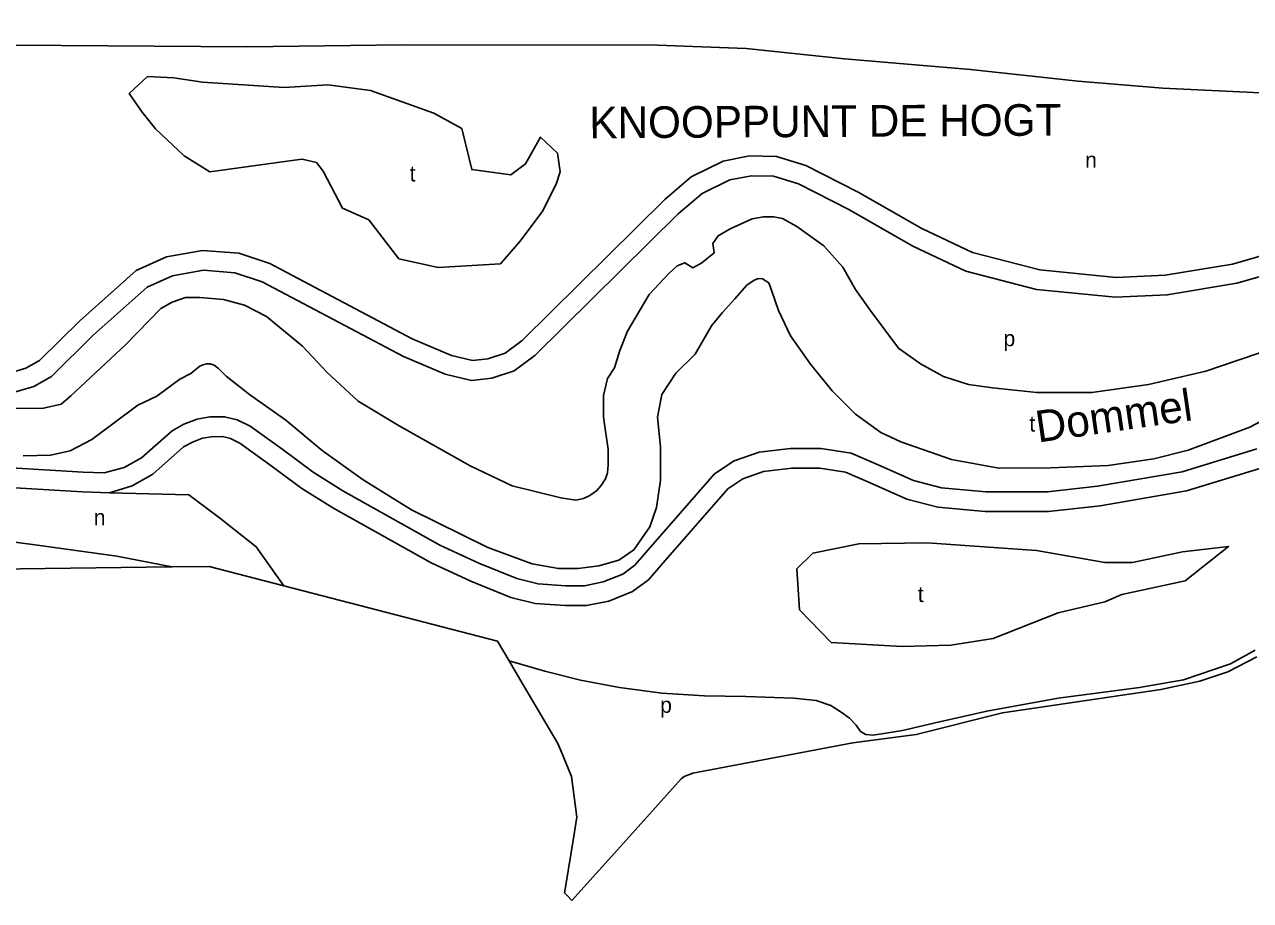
# Model space of a CAD drawing. Extents: x 157646 to 159241, y 379213 to 381217.
# Drawn here: x 157924.6 to 158234.9, y 379212.5 to 379434.4 of the extents above; entities that cross this region are included whole.
import ezdxf

# ---------------------------------------------------------------- set-up
doc = ezdxf.new("R2010")
doc.units = 0
for name, color, linetype in [('BLT_Basislijn', 7, 'Continuous'), ('BLT_Centroide', 7, 'Continuous'), ('BLT_Gemeentegrens', 7, 'Continuous'), ('BLT_Straatnaam_hoofdweg', 7, 'Continuous'), ('BLT_Vlakafsluiter', 7, 'Continuous'), ('BLT_Waternaam_spoorwegen', 7, 'Continuous')]:
    doc.layers.add(name, color=color, linetype=linetype)

msp = doc.modelspace()

# ---------------------------------------------------------------- linework, layer by layer
at = {"layer": 'BLT_Basislijn'}
for points in [[(158308.08, 379434.36), (158304.89, 379420.42), (158304.51, 379418.26), (158303.7, 379416.73), (158301.68, 379415.14), (158298.37, 379414.29), (158293.42, 379414.16), (158286.33, 379415.05), (158269.88, 379415.95), (158256.93, 379416.11), (158212.73, 379418.23), (158191.26, 379420.04), (158164.06, 379422.99), (158132.14, 379425.65), (158107.23, 379428.27), (158084.78, 379429.09), (158020.06, 379429.21), (157981.06, 379428.72), (157922.04, 379429.13), (157868.95, 379431.58), (157838.47, 379433.55)], [(158327.61, 379415.93), (158321.88, 379409.59), (158317.43, 379405.76), (158308.19, 379397.05), (158298.53, 379387.87), (158285.32, 379377.1), (158270.25, 379367.26), (158255.08, 379358.93), (158240.75, 379352.37), (158223.61, 379346.56), (158209.1, 379343.19), (158194.77, 379341.2)], [(158146.42, 379328.7), (158159.26, 379324.21), (158171.21, 379321.96), (158184.25, 379322.05), (158198.87, 379322.69), (158210.48, 379324.39), (158219.12, 379326.55), (158234.71, 379332.37), (158245.04, 379337.84), (158250.49, 379341.13), (158261.45, 379345.82), (158270.62, 379350.97), (158279.05, 379356.03), (158293.9, 379365.97), (158305.21, 379374.66), (158315.7, 379383.84), (158326.35, 379393.02), (158334.71, 379401.71), (158339.91, 379408.18)], [(158247.02, 379378.45), (158230.37, 379373.7), (158213.33, 379370.84), (158200.9, 379370.28), (158181.63, 379372.19), (158164.55, 379376.61), (158151.73, 379382.69), (158135.6, 379391.87), (158122.39, 379398.68), (158114.93, 379400.97), (158108.12, 379401.06), (158101.47, 379399.75), (158093.37, 379395.75), (158086.64, 379390.07), (158050.52, 379354.31), (158046.22, 379351.13), (158041.84, 379349.72), (158037.99, 379349.25), (158032.66, 379350.54), (158022.68, 379354.79), (157986.71, 379373.84), (157978.81, 379376.41), (157969.64, 379377.14), (157960.56, 379375.52), (157952.88, 379372.04), (157938.58, 379359.29), (157928.37, 379349.26), (157924.96, 379347.3), (157920.44, 379346)], [(158248.63, 379373.71), (158231.48, 379368.82), (158213.86, 379365.86), (158200.76, 379365.27), (158180.75, 379367.25), (158162.84, 379371.88), (158149.42, 379378.26), (158133.22, 379387.47), (158120.49, 379394.03), (158114.14, 379395.98), (158108.58, 379396.05), (158103.09, 379394.98), (158096.13, 379391.53), (158090.02, 379386.38), (158053.78, 379350.5), (158048.53, 379346.62), (158042.91, 379344.81), (158037.7, 379344.18), (158031.08, 379345.78), (158020.53, 379350.27), (157984.75, 379369.22), (157977.82, 379371.48), (157969.88, 379372.11), (157962.06, 379370.71), (157955.63, 379367.8), (157942, 379355.64), (157931.42, 379345.25), (157926.93, 379342.66), (157921.48, 379341.1)], [(158194.77, 379341.2), (158180.83, 379341.2), (158169.64, 379342.37), (158163.5, 379343.17), (158157.23, 379345.17), (158151.38, 379348.39), (158145.79, 379352.37), (158138.68, 379362), (158134.91, 379367.21), (158131.73, 379372.89), (158126.94, 379378.27), (158120.09, 379383.24), (158116.43, 379385.23), (158114.23, 379385.69), (158111.61, 379385.69), (158108.81, 379385.13), (158103.18, 379382.65), (158100.17, 379380.81), (158098.85, 379378.9), (158099.18, 379376.53), (158096.01, 379374.03), (158093.75, 379372.75), (158091.72, 379374.03), (158089.76, 379373.21), (158087.65, 379371.33), (158082.73, 379365.95), (158077.23, 379356.68), (158075.27, 379351.76), (158073.94, 379347.38), (158072.15, 379344.69), (158071.17, 379340.41), (158071.17, 379334.95), (158072.35, 379326.7), (158072.35, 379322.81), (158072.15, 379320.8), (158071.66, 379319.29), (158070.58, 379317.62), (158069.36, 379316.22), (158067.72, 379315.04), (158066.06, 379314.32), (158064.15, 379313.93), (158060.34, 379314.44), (158048.01, 379317.56), (158037.42, 379322.56), (158019.46, 379332.71), (158009.01, 379338.98), (158001.17, 379346.26), (157994.94, 379352.87), (157985.81, 379360.44), (157980.27, 379363.27), (157974.97, 379364.7), (157968.96, 379365.24), (157965.31, 379365.24), (157961.94, 379364.07), (157959.11, 379362.4), (157950.13, 379353.2), (157936.34, 379340.33), (157933.85, 379338.23), (157929.42, 379337.15), (157912.66, 379337.04)], [(157924.23, 379325.09), (157931.14, 379325.29), (157936.16, 379326.4), (157941.62, 379329.24), (157953.27, 379337.93), (157958.09, 379340.19), (157963.93, 379344.56), (157966.68, 379345.96), (157968.15, 379347.19), (157968.96, 379347.86), (157969.69, 379348.17), (157970.72, 379348.46), (157971.58, 379348.46), (157972.63, 379348.07), (157973.65, 379347.24), (157975.66, 379345.29), (157981.53, 379340.66), (157990.75, 379334.15), (157999.91, 379326.47), (158010.33, 379319.05), (158022.55, 379311.45), (158041.83, 379301.88), (158053.05, 379297.79), (158059.78, 379296.61), (158064.7, 379296.61), (158069.95, 379297.24), (158074.99, 379298.73), (158078.84, 379301.35), (158082.87, 379307.17), (158084.52, 379312.04), (158085.54, 379318.95), (158085.54, 379327.37), (158084.84, 379334.87), (158085.94, 379340.63), (158089.43, 379346.09), (158094.34, 379350.88), (158098.49, 379358), (158101.17, 379361.3), (158104.41, 379364.84), (158107.46, 379368.3), (158109.25, 379369.63), (158110.35, 379370.03), (158111.42, 379369.93), (158112.97, 379368.91), (158113.79, 379366.83), (158115.48, 379361.91), (158118.44, 379355.52), (158123.51, 379348.36), (158129.01, 379341.57), (158134.89, 379335.68), (158141.32, 379331.05), (158146.42, 379328.7)], [(157944.76, 379320.81), (157949.85, 379322.16), (157954.2, 379324.57), (157961.94, 379331.44), (157964.94, 379333.15), (157968.31, 379334.43), (157971.48, 379334.97), (157975.22, 379335.02), (157978.45, 379334.27), (157981.71, 379332.63), (157989.68, 379326.88), (157997.61, 379320.94), (158005.17, 379316.24), (158029.75, 379302.46), (158039.57, 379297.96), (158049.21, 379294.03), (158054.6, 379292.68), (158061.64, 379292.23), (158066.32, 379292.23), (158071.02, 379293.17), (158076.04, 379295.19), (158079.1, 379297.41), (158081.87, 379300.61), (158099.25, 379320.55), (158104.21, 379323.83), (158110.53, 379326.04), (158118.51, 379326.99), (158126.27, 379326.99), (158133.82, 379325.81), (158140.63, 379322.83), (158149.58, 379318.87), (158156.67, 379317.03), (158167.95, 379316.01), (158183.53, 379316.01), (158196.19, 379317.43), (158217.58, 379321.1), (158236.53, 379326.93)], [(157946.11, 379315.77), (157951.82, 379317.54), (157957.1, 379320.46), (157964.87, 379327.36), (157967.08, 379328.61), (157969.63, 379329.58), (157971.94, 379329.97), (157974.69, 379330.01), (157976.74, 379329.54), (157979.1, 379328.34), (157986.72, 379322.85), (157994.78, 379316.81), (158002.62, 379311.93), (158027.49, 379298), (158037.58, 379293.37), (158047.65, 379289.27), (158053.82, 379287.72), (158061.48, 379287.23), (158066.81, 379287.23), (158072.46, 379288.35), (158078.47, 379290.78), (158082.51, 379293.7), (158085.65, 379297.34), (158102.58, 379316.75), (158106.45, 379319.32), (158111.66, 379321.14), (158118.8, 379321.99), (158125.88, 379321.99), (158132.4, 379320.97), (158138.62, 379318.26), (158147.93, 379314.13), (158155.81, 379312.08), (158167.73, 379311.01), (158183.81, 379311.01), (158196.9, 379312.48), (158218.74, 379316.23), (158238.35, 379322.26)], [(157944.76, 379320.81), (157939.45, 379320.96), (157907.19, 379322.91), (157903.78, 379324.85)], [(157946.11, 379315.77), (157939.23, 379315.96), (157895, 379318.64), (157887.64, 379318.07), (157883.7, 379317.39), (157875.86, 379315.31), (157863.35, 379310.25), (157856.55, 379306.5), (157845.17, 379299.37), (157834.47, 379289.65), (157828.74, 379284.25)], [(157990.23, 379292.2), (157983.24, 379302.09), (157973.97, 379309.4), (157966.2, 379315.2), (157946.11, 379315.77)], [(157891.3, 379296.08), (157890.11, 379299.68), (157890.11, 379302.47), (157891.04, 379305), (157892.64, 379306.19), (157894.9, 379306.06), (157909.4, 379304.86), (157926.03, 379302.73), (157947.97, 379299.68), (157961.86, 379297.01)], [(158236.09, 379275.92), (158229.85, 379272.47), (158217.97, 379268.42), (158206.82, 379266.47), (158186.23, 379263.72), (158168.15, 379260.47), (158156.23, 379257.76), (158146.82, 379255.57), (158141.59, 379254.71), (158139.32, 379254.39), (158137.58, 379254.51), (158136.2, 379255.32), (158135.07, 379256.9), (158133.4, 379258.65), (158131.34, 379260.23), (158128.66, 379261.85), (158125.01, 379263.19), (158119.34, 379263.76), (158107.17, 379264.2), (158096.75, 379264.36), (158085.93, 379264.97), (158075.23, 379266.47), (158065.33, 379268.26), (158056.29, 379270.57), (158047.25, 379273.22)], [(158061.92, 379213.76), (158061.94, 379213.71)]]:
    msp.add_lwpolyline(points, dxfattribs=at)
for points in [[(158029.27, 379372.83), (158019.37, 379375.05), (158011.73, 379384.86), (158005.06, 379387.84), (158000.19, 379397.2), (157998.47, 379399.42), (157994.87, 379400.24), (157992.91, 379400.04), (157971.47, 379397.06), (157964.98, 379401.07), (157957.72, 379407.91), (157954.35, 379412.12), (157951.08, 379416.9), (157955.73, 379421.19), (157962.35, 379420.87), (157969.6, 379419.73), (157990.27, 379418.41), (158001.39, 379419.09), (158012.19, 379417.68), (158028.19, 379411.9), (158035.31, 379407.99), (158037.78, 379397.61), (158047.67, 379396.3), (158051.4, 379399.05), (158055.22, 379405.85), (158059.51, 379401.78), (158060.16, 379397.04), (158059.14, 379393.92), (158055.61, 379386.92), (158049.97, 379379.41), (158045.04, 379373.75)], [(158124.12, 379300.46), (158135.77, 379302.79), (158153.09, 379303.12), (158180.73, 379301.12), (158198.05, 379298.13), (158205.04, 379298.13), (158217.7, 379300.79), (158229.35, 379302.12), (158218.36, 379293.47), (158202.33, 379290.01), (158198.05, 379288.14), (158186.19, 379285.35), (158169.74, 379278.82), (158159.08, 379277.15), (158146.76, 379276.82), (158128.78, 379277.82), (158120.79, 379286.14), (158120.12, 379296.46)]]:
    msp.add_lwpolyline(points, close=True, dxfattribs=at)
at = {"layer": 'BLT_Gemeentegrens'}
for points in [[(157891.3, 379296.08), (157961.86, 379297.01)], [(157961.86, 379297.01), (157971.31, 379297.13), (157990.23, 379292.2)], [(157990.23, 379292.2), (158000, 379289.65), (158044.34, 379278.14), (158047.25, 379273.22)], [(158047.25, 379273.22), (158050, 379268.54), (158059.59, 379252.27), (158060.32, 379250.52), (158063.08, 379243.94), (158064.41, 379233.61), (158063.63, 379228.79), (158061.47, 379215.4), (158061.31, 379214.42), (158061.92, 379213.76), (158063.11, 379212.5), (158076.98, 379227.9), (158090.84, 379243.3), (158091.58, 379243.91), (158093.78, 379244.78), (158134.23, 379252.45), (158150.32, 379254.5), (158172.13, 379260.03), (158212.25, 379265.92), (158222.13, 379268.01), (158229.21, 379270.42), (158236.51, 379274.18)]]:
    msp.add_lwpolyline(points, dxfattribs=at)
at = {"layer": 'BLT_Vlakafsluiter'}
msp.add_line((158061.44, 379215.39), (158061.47, 379215.4), dxfattribs=at)

# ---------------------------------------------------------------- texts
at = {"layer": 'BLT_Centroide'}
for s, p in [('n', (158193.05, 379398.06)), ('t', (158022.08, 379394.6)), ('p', (158172.39, 379352.87)), ('t', (158178.94, 379331.25)), ('n', (157942.11, 379307.55)), ('t', (158150.71, 379288.08)), ('p', (158085.48, 379260.03))]:
    msp.add_text(s, height=4, dxfattribs=at).set_placement(p)
at = {"layer": 'BLT_Straatnaam_hoofdweg'}
msp.add_text('KNOOPPUNT DE HOGT', height=8, rotation=0.3405, dxfattribs=at).set_placement((158067.58, 379405.52))
at = {"layer": 'BLT_Waternaam_spoorwegen'}
msp.add_text('Dommel', height=8, rotation=8.2296, dxfattribs=at).set_placement((158181.14, 379328.47))

doc.saveas('drawing.dxf')
